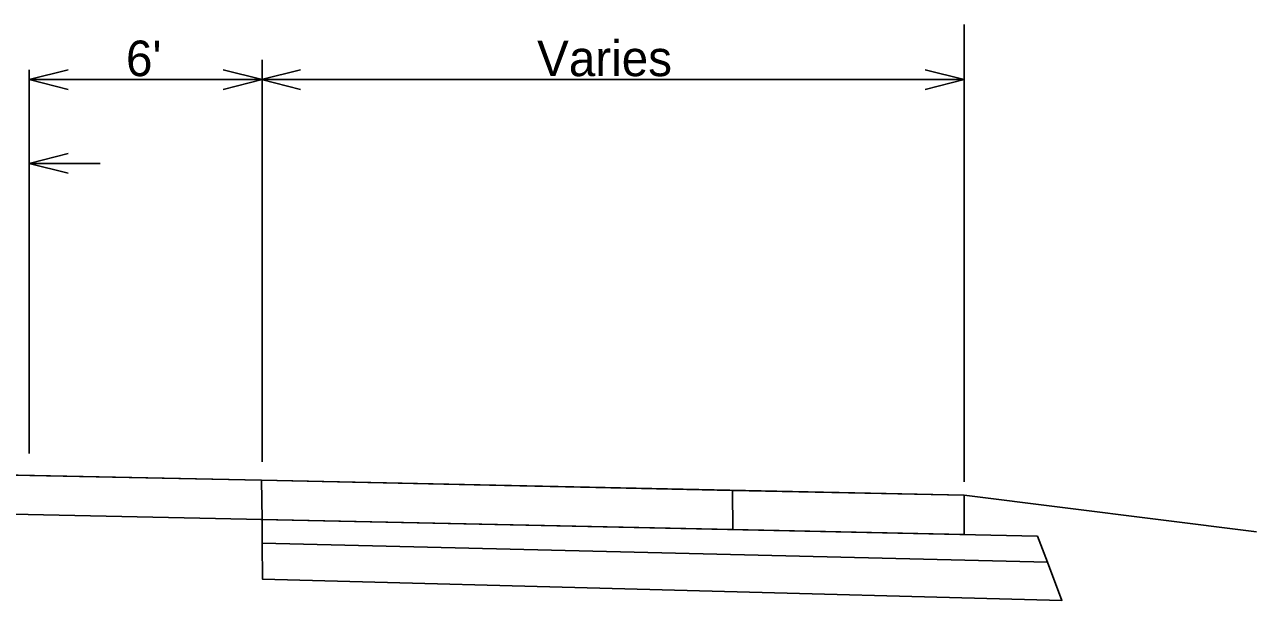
# Model space of a CAD drawing. Extents: x 10133 to 81668, y 4856 to 11018.
# Drawn here: x 11799 to 12318, y 9131 to 9374 of the extents above; entities that cross this region are included whole.
import ezdxf

# ---------------------------------------------------------------- set-up
doc = ezdxf.new("R2010")
doc.units = 0
for name, color, linetype in [('dsnStdDimension', 7, 'Continuous'), ('dsnXsPCCPavementBottom', 7, 'Continuous'), ('dsnXsShldrEarthFill', 7, 'Continuous'), ('dsnXsShldrGranular', 7, 'Continuous'), ('dsnXsShldrGranularBottom', 7, 'Continuous'), ('dsnXsShldrSpecialBackBottom', 7, 'Continuous')]:
    doc.layers.add(name, color=color, linetype=linetype)

msp = doc.modelspace()

# ---------------------------------------------------------------- linework, layer by layer
at = {"layer": 'dsnStdDimension'}
for p, q in [((12225.54, 9157.78), (11898.67, 9164.73)), ((12229.68, 9146.73), (12225.54, 9157.78)), ((11898.67, 9154.83), (12229.68, 9146.73))]:
    msp.add_line(p, q, dxfattribs=at)
msp.add_lwpolyline([(11898.67, 9164.73), (11898.67, 9164.73), (11898.67, 9154.83), (11898.67, 9154.83)], dxfattribs=at)
msp.add_lwpolyline([(11898.67, 9154.83), (11898.67, 9154.83), (12229.68, 9146.73), (12235.75, 9130.66), (11898.89, 9139.57), (11898.89, 9139.57)], close=True, dxfattribs=at)
at = {"layer": 'dsnXsPCCPavementBottom'}
for p, q in [((12194.51, 9180.71), (12194.51, 9373.54)), ((11898.67, 9196.79), (11898.67, 9358.65)), ((11898.67, 9358.65), (11898.67, 9189.04)), ((11800.5, 9354.43), (11800.5, 9192.57)), ((11898.67, 9350.33), (11800.5, 9350.33)), ((12194.51, 9350.33), (11898.43, 9350.33)), ((11830.4, 9315.01), (11800.5, 9315.01))]:
    msp.add_line(p, q, dxfattribs=at)
for points in [[(11816.89, 9346.24), (11800.5, 9350.33), (11816.89, 9354.43)], [(11882.28, 9346.24), (11898.67, 9350.33), (11882.28, 9354.43)], [(11914.82, 9346.24), (11898.43, 9350.33), (11914.82, 9354.43)], [(12178.12, 9354.43), (12194.51, 9350.33), (12178.12, 9346.24)], [(11816.89, 9310.91), (11800.5, 9315.01), (11816.89, 9319.11)]]:
    msp.add_lwpolyline(points, dxfattribs=at)
at = {"layer": 'dsnXsShldrGranular'}
msp.add_line((11898.67, 9164.73), (11699.65, 9168.96), dxfattribs=at)
msp.add_lwpolyline([(11700, 9185.51), (11898.43, 9181.3), (11898.67, 9164.73)], dxfattribs=at)
for points in [[(11898.43, 9181.3), (12096.87, 9177.08), (12097.11, 9160.51), (11898.67, 9164.73)], [(12194.62, 9175), (12096.87, 9177.08), (12097.11, 9160.51), (12194.62, 9158.4)]]:
    msp.add_lwpolyline(points, close=True, dxfattribs=at)
at = {"layer": 'dsnXsShldrGranularBottom'}
for p, q in [((11700, 9185.51), (11898.43, 9181.3)), ((11898.43, 9181.3), (11898.67, 9164.73)), ((11898.43, 9181.3), (12194.62, 9175)), ((12096.87, 9177.08), (12097.11, 9160.51)), ((12096.87, 9177.08), (12097.11, 9160.51)), ((12096.87, 9177.08), (12097.11, 9160.51)), ((12194.62, 9175), (12317.73, 9159.53)), ((11699.65, 9168.96), (11898.67, 9164.73)), ((11898.08, 9164.74), (12194.63, 9158.44))]:
    msp.add_line(p, q, dxfattribs=at)
at = {"layer": 'dsnXsShldrSpecialBackBottom'}
msp.add_line((12194.62, 9175), (12194.62, 9158.4), dxfattribs=at)

# ---------------------------------------------------------------- texts
at = {"layer": 'dsnXsShldrEarthFill'}
for s, p in [("6'", (11841.31, 9351.8)), ('Varies', (12014.58, 9351.8))]:
    msp.add_text(s, height=15, dxfattribs=at).set_placement(p)

doc.saveas('drawing.dxf')
